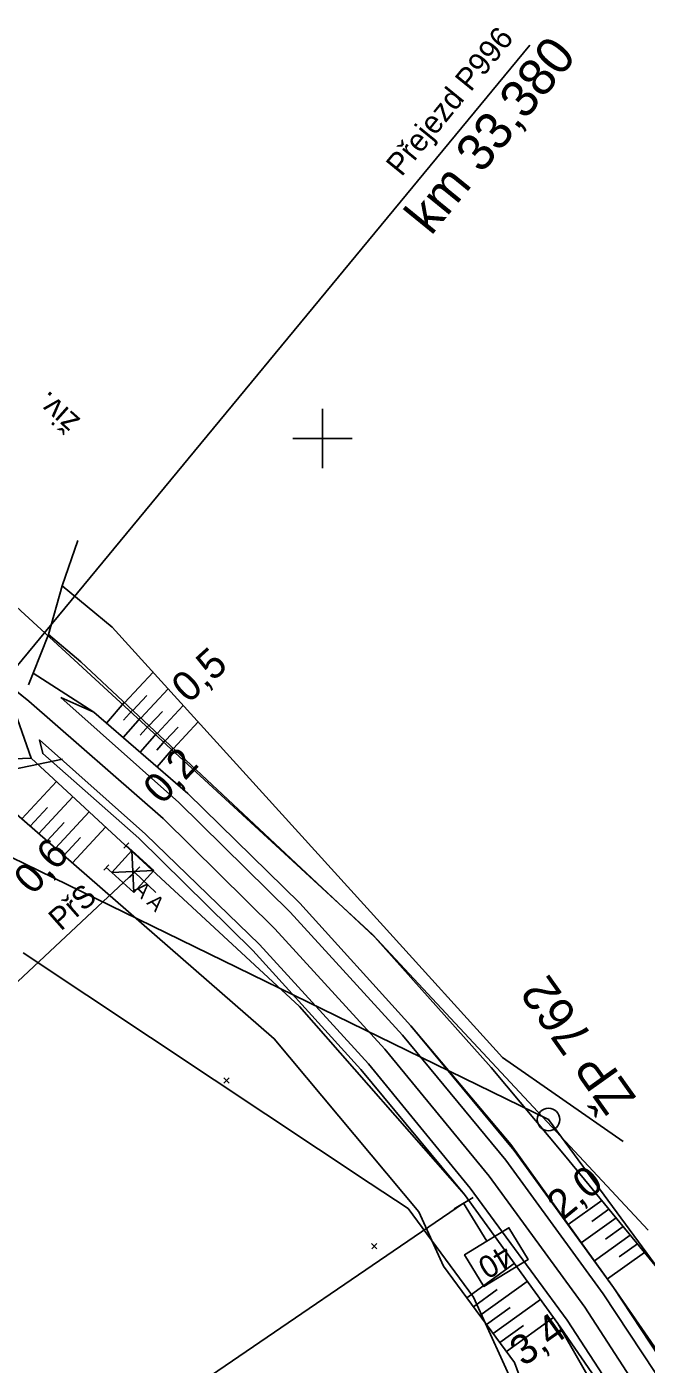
# Model space of a CAD drawing. Extents: x -805011 to -803920, y -1150790 to -1150234.
# Drawn here: x -804219.9 to -804178.2, y -1150562.3 to -1150472.3 of the extents above; entities that cross this region are included whole.
import ezdxf

# ---------------------------------------------------------------- set-up
doc = ezdxf.new("R2010")
doc.units = 0
for name, color, linetype in [('0381KM032-037P - Vrstva 1', 7, 'Continuous'), ('0381KM032-037P - Vrstva 4', 7, 'Continuous'), ('0381KM032-037P - Vrstva 48', 7, 'Continuous'), ('0381KM032-037P - Vrstva 49', 7, 'Continuous'), ('0381KM032-037P - Vrstva 5', 7, 'Continuous'), ('0381KM032-037P - Vrstva 51', 7, 'Continuous'), ('0381KM032-037P - Vrstva 6', 7, 'Continuous'), ('0381KM032-037P - Vrstva 7', 7, 'Continuous'), ('hran DP - hran DP', 7, 'Continuous'), ('krizky_1000 - Vrstva 1', 7, 'Continuous'), ('vyt_sit - ohrožené', 7, 'Continuous'), ('vyt_sit - polygon', 7, 'Continuous')]:
    doc.layers.add(name, color=color, linetype=linetype)

msp = doc.modelspace()

# ---------------------------------------------------------------- linework, layer by layer
at = {"layer": '0381KM032-037P - Vrstva 1'}
msp.add_lwpolyline([(-804170.822, -1150577.298), (-804176.258, -1150567.853), (-804182.371, -1150558.448), (-804188.8, -1150549.629), (-804195.802, -1150541.086), (-804203.2, -1150532.984), (-804210.727, -1150525.566), (-804219.762, -1150517.68), (-804222.979, -1150515.095)], dxfattribs=at)
at = {"layer": '0381KM032-037P - Vrstva 4'}
for p, q in [((-804186.062, -1150473.536), (-804222.057, -1150517.116)), ((-804219.762, -1150517.68), (-804222.979, -1150515.095)), ((-804222.005, -1150522.509), (-804217.491, -1150521.573))]:
    msp.add_line(p, q, dxfattribs=at)
for points in [[(-804187.111, -1150547.908), (-804194.057, -1150539.524), (-804201.534, -1150531.257), (-804209.073, -1150523.878), (-804215.386, -1150518.402), (-804217.606, -1150517.412)], [(-804187.677, -1150548.561), (-804194.635, -1150540.132), (-804202.18, -1150531.866), (-804209.673, -1150524.484), (-804217.606, -1150517.412)], [(-804190.063, -1150550.442), (-804196.905, -1150542.065), (-804204.246, -1150534.035), (-804211.902, -1150526.624), (-804219.035, -1150520.275), (-804218.825, -1150521.196), (-804212.362, -1150526.896), (-804204.686, -1150534.438)], [(-804204.686, -1150534.438), (-804197.425, -1150542.443), (-804190.457, -1150550.873)], [(-804155.31, -1150604.52), (-804159.649, -1150594.756), (-804164.129, -1150585.172), (-804168.865, -1150576.083), (-804174.28, -1150566.446), (-804180.439, -1150557.113), (-804187.111, -1150547.908)], [(-804155.958, -1150604.81), (-804160.35, -1150595.071), (-804164.873, -1150585.497), (-804169.431, -1150576.623), (-804175.01, -1150566.818), (-804181.125, -1150557.549), (-804187.677, -1150548.561)], [(-804159.667, -1150606.247), (-804163.987, -1150596.782), (-804168.29, -1150587.201), (-804172.877, -1150578.495), (-804178.084, -1150568.907), (-804181.433, -1150563.503), (-804184.179, -1150559.55), (-804190.457, -1150550.873)], [(-804158.943, -1150605.891), (-804163.074, -1150596.409), (-804167.658, -1150586.765), (-804172.113, -1150577.988), (-804177.545, -1150568.561), (-804183.558, -1150559.317), (-804190.063, -1150550.442)]]:
    msp.add_lwpolyline(points, dxfattribs=at)
at = {"layer": '0381KM032-037P - Vrstva 48'}
for p, q in [((-804213.32, -1150517.783), (-804211.39, -1150515.723)), ((-804212.225, -1150518.809), (-804210.379, -1150516.838)), ((-804213.339, -1150517.765), (-804214.533, -1150519.142)), ((-804212.772, -1150518.296), (-804211.829, -1150517.288)), ((-804212.243, -1150518.791), (-804213.4, -1150520.125)), ((-804212.791, -1150518.278), (-804213.379, -1150518.956)), ((-804211.678, -1150519.321), (-804210.776, -1150518.358)), ((-804211.13, -1150519.834), (-804209.368, -1150517.953)), ((-804211.696, -1150519.304), (-804212.265, -1150519.96)), ((-804210.583, -1150520.347), (-804209.723, -1150519.428)), ((-804210.035, -1150520.859), (-804208.358, -1150519.068)), ((-804211.148, -1150519.817), (-804212.267, -1150521.108)), ((-804210.6, -1150520.33), (-804211.15, -1150520.965)), ((-804210.052, -1150520.843), (-804211.134, -1150522.09)), ((-804220.222, -1150525.587), (-804217.903, -1150523.081)), ((-804219.091, -1150526.573), (-804216.802, -1150524.1)), ((-804219.656, -1150526.08), (-804218.504, -1150524.835)), ((-804218.525, -1150527.066), (-804217.388, -1150525.838)), ((-804217.959, -1150527.559), (-804215.701, -1150525.119)), ((-804217.394, -1150528.052), (-804216.272, -1150526.84)), ((-804216.828, -1150528.545), (-804214.6, -1150526.138)), ((-804181.215, -1150551.268), (-804183.472, -1150552.889)), ((-804180.738, -1150551.849), (-804181.886, -1150552.674)), ((-804180.261, -1150552.43), (-804182.597, -1150554.107)), ((-804179.784, -1150553.011), (-804180.972, -1150553.864)), ((-804179.307, -1150553.592), (-804181.722, -1150555.326)), ((-804178.353, -1150554.754), (-804180.847, -1150556.544)), ((-804178.83, -1150554.173), (-804180.057, -1150555.054)), ((-804190.305, -1150557.806), (-804187.112, -1150555.496)), ((-804189.859, -1150558.409), (-804188.266, -1150557.257)), ((-804189.413, -1150559.013), (-804186.233, -1150556.711)), ((-804188.522, -1150560.219), (-804185.354, -1150557.927)), ((-804188.968, -1150559.616), (-804187.381, -1150558.468)), ((-804187.631, -1150561.426), (-804184.474, -1150559.142)), ((-804188.077, -1150560.823), (-804186.495, -1150559.679))]:
    msp.add_line(p, q, dxfattribs=at)
at = {"layer": '0381KM032-037P - Vrstva 49'}
for p, q in [((-804218.43, -1150513.19), (-804217.51, -1150509.9)), ((-804214.14, -1150512.69), (-804217.51, -1150509.9)), ((-804218.43, -1150513.19), (-804219.465, -1150515.789)), ((-804216.26, -1150515.03), (-804218.43, -1150513.19)), ((-804220.84, -1150517.99), (-804219.6, -1150521.51)), ((-804219.6, -1150521.51), (-804222.65, -1150521.62)), ((-804206.644, -1150543.012), (-804206.29, -1150543.364)), ((-804206.291, -1150543.011), (-804206.643, -1150543.365)), ((-804196.699, -1150554.165), (-804196.345, -1150554.517)), ((-804196.346, -1150554.164), (-804196.698, -1150554.518))]:
    msp.add_line(p, q, dxfattribs=at)
for points in [[(-804179.775, -1150547.299), (-804187.894, -1150541.654), (-804195.903, -1150532.804), (-804214.14, -1150512.69)], [(-804216.26, -1150515.03), (-804196.494, -1150533.54), (-804188.661, -1150542.31), (-804183.721, -1150548.216), (-804176.998, -1150556.404), (-804165.664, -1150573.065), (-804155.488, -1150590.499), (-804146.445, -1150604.861), (-804136.373, -1150622.314), (-804131.913, -1150629.82), (-804122.713, -1150645.636), (-804115.713, -1150666.787), (-804102.893, -1150677.063), (-804092.506, -1150687.924), (-804076.709, -1150692.971), (-804062.718, -1150701.966), (-804052.08, -1150706.52)], [(-804194.057, -1150539.524), (-804201.534, -1150531.257), (-804209.073, -1150523.878), (-804215.386, -1150518.402), (-804219.465, -1150515.789)], [(-804190.457, -1150550.873), (-804201.544, -1150538.223), (-804219.6, -1150521.51)], [(-804191.878, -1150555.675), (-804193.532, -1150552.027), (-804203.252, -1150540.379), (-804221.09, -1150524.83)], [(-804177.463, -1150561.393), (-804180.439, -1150557.113), (-804187.342, -1150547.499), (-804194.057, -1150539.524)], [(-804190.457, -1150550.873), (-804184.179, -1150559.55), (-804171.889, -1150581.005)], [(-804191.878, -1150555.675), (-804187.094, -1150562.154), (-804183.466, -1150572.059), (-804177.466, -1150586.829), (-804171.323, -1150602.684), (-804162.19, -1150629.627), (-804127.409, -1150694.052), (-804117.854, -1150694.755), (-804107.487, -1150702.042), (-804103.027, -1150704.725), (-804070.42, -1150728.33), (-804053.81, -1150732.63), (-804001.622, -1150732.392)]]:
    msp.add_lwpolyline(points, dxfattribs=at)
at = {"layer": '0381KM032-037P - Vrstva 5'}
for p, q in [((-804189.878, -1150551.056), (-804191.16, -1150551.836)), ((-804190.519, -1150551.446), (-804225.169, -1150575.08))]:
    msp.add_line(p, q, dxfattribs=at)
msp.add_lwpolyline([(-804190.519, -1150551.446), (-804188.959, -1150554.008), (-804190.454, -1150554.918), (-804189.154, -1150557.054), (-804186.164, -1150555.234), (-804187.464, -1150553.098), (-804188.959, -1150554.008)], dxfattribs=at)
at = {"layer": '0381KM032-037P - Vrstva 51'}
msp.add_lwpolyline([(-804219.78, -1150516.58), (-804219.465, -1150515.789), (-804218.43, -1150513.19), (-804217.51, -1150509.9), (-804216.47, -1150506.86)], dxfattribs=at)
at = {"layer": '0381KM032-037P - Vrstva 6'}
for p, q in [((-804212.64, -1150529.17), (-804242.831, -1150557.407)), ((-804212.295, -1150528.808), (-804212.985, -1150529.532)), ((-804211.207, -1150530.537), (-804212.64, -1150529.17))]:
    msp.add_line(p, q, dxfattribs=at)
at = {"layer": '0381KM032-037P - Vrstva 7'}
for p, q in [((-804212.83, -1150527.713), (-804214.176, -1150529.192)), ((-804213.368, -1150527.561), (-804213.032, -1150527.191)), ((-804212.83, -1150527.713), (-804213.2, -1150527.376)), ((-804212.83, -1150527.713), (-804211.351, -1150529.058)), ((-804212.83, -1150527.713), (-804212.696, -1150530.538)), ((-804214.714, -1150529.041), (-804214.378, -1150528.671)), ((-804214.176, -1150529.192), (-804214.546, -1150528.856)), ((-804211.351, -1150529.058), (-804214.176, -1150529.192)), ((-804214.176, -1150529.192), (-804212.696, -1150530.538)), ((-804211.351, -1150529.058), (-804212.696, -1150530.538))]:
    msp.add_line(p, q, dxfattribs=at)
at = {"layer": 'hran DP - hran DP'}
for p, q in [((-804221.41, -1150510.55), (-804216.71, -1150514.88)), ((-804216.71, -1150514.88), (-804196.65, -1150533.37)), ((-804196.65, -1150533.37), (-804178.11, -1150553.27)), ((-804207.3, -1150543.14), (-804220.13, -1150534.61)), ((-804196.79, -1150550.13), (-804207.3, -1150543.14)), ((-804194.25, -1150551.81), (-804196.79, -1150550.13)), ((-804189.84, -1150557.76), (-804194.25, -1150551.81)), ((-804182.55, -1150573.8), (-804189.84, -1150557.76))]:
    msp.add_line(p, q, dxfattribs=at)
at = {"layer": 'krizky_1000 - Vrstva 1'}
for points in [[(-804200, -1150498), (-804200, -1150502)], [(-804202, -1150500), (-804198, -1150500)]]:
    msp.add_lwpolyline(points, dxfattribs=at)
at = {"layer": 'vyt_sit - ohrožené'}
msp.add_line((-804184.857, -1150545.814), (-804184.757, -1150545.814), dxfattribs=at)
msp.add_circle((-804184.807, -1150545.814), 0.756, dxfattribs=at)
at = {"layer": 'vyt_sit - polygon'}
for p, q in [((-804328.266, -1150475.773), (-804184.807, -1150545.814)), ((-804184.807, -1150545.814), (-804054.717, -1150722.824))]:
    msp.add_line(p, q, dxfattribs=at)

# ---------------------------------------------------------------- texts
at = {"layer": '0381KM032-037P - Vrstva 4'}
for s, height, p in [('Přejezd P996', 1.5, (-804194.688, -1150482.434)), ('km 33,380', 2.5, (-804192.704, -1150486.405))]:
    msp.add_text(s, height=height, rotation=50.85601, dxfattribs=at).set_placement(p)
at = {"layer": '0381KM032-037P - Vrstva 48'}
for s, rotation, p in [('0,5', 42.19803, (-804209.021, -1150517.877)), ('0,2', 46.87945, (-804210.786, -1150524.7)), ('0,6', 47.21203, (-804219.477, -1150530.781)), ('2,0', 39.38872, (-804183.859, -1150552.669)), ('3,4', 35.33808, (-804186.488, -1150562.479))]:
    msp.add_text(s, height=2, rotation=rotation, dxfattribs=at).set_placement(p)
at = {"layer": '0381KM032-037P - Vrstva 5'}
msp.add_text('40', height=1.5, rotation=211.33438, dxfattribs=at).set_placement((-804187.789, -1150554.174))
at = {"layer": '0381KM032-037P - Vrstva 51'}
msp.add_text('živ.', height=1.5, rotation=138.29657, dxfattribs=at).set_placement((-804216.224, -1150498.714))
at = {"layer": '0381KM032-037P - Vrstva 6'}
for s, height, rotation, p in [('PřS', 1.5, 41.34441, (-804217.599, -1150533.182)), ('  A A ', 1, 316.34441, (-804213.33, -1150529.894))]:
    msp.add_text(s, height=height, rotation=rotation, dxfattribs=at).set_placement(p)
at = {"layer": 'vyt_sit - ohrožené'}
msp.add_text('ŽP 762', height=2.4, rotation=125.43858, dxfattribs=at).set_placement((-804178.853, -1150544.364))

doc.saveas('drawing.dxf')
